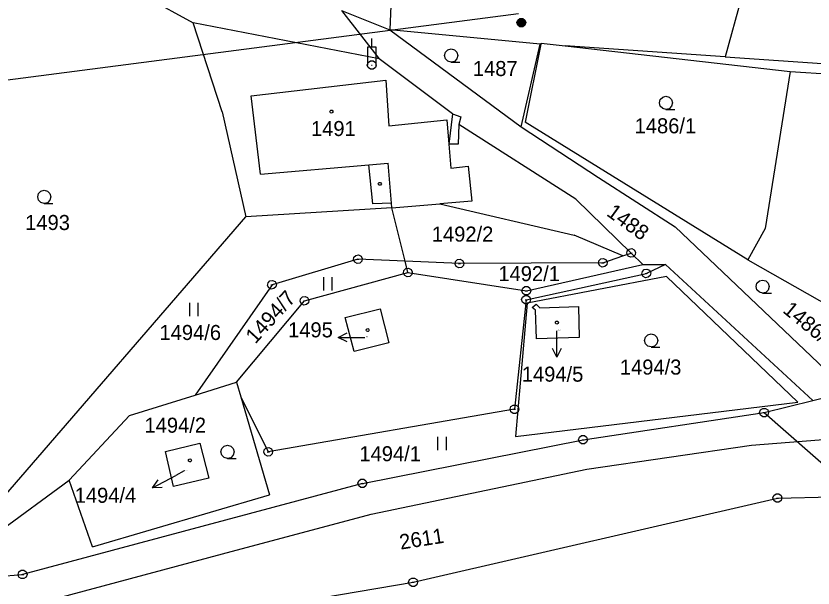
# Model space of a CAD drawing. Extents: x -806774 to -803680, y -1151731 to -1150053.
# Drawn here: x -805353.1 to -805263, y -1150678 to -1150613.4 of the extents above; entities that cross this region are included whole.
import ezdxf

# ---------------------------------------------------------------- set-up
doc = ezdxf.new("R2010")
doc.units = 0
for name, color, linetype in [('1', 7, 'Continuous'), ('12', 7, 'Continuous'), ('2', 7, 'Continuous'), ('3', 7, 'Continuous'), ('4', 7, 'Continuous'), ('5', 7, 'Continuous'), ('6', 7, 'Continuous'), ('7', 7, 'Continuous'), ('8', 7, 'Continuous')]:
    doc.layers.add(name, color=color, linetype=linetype)

msp = doc.modelspace()

# ---------------------------------------------------------------- linework, layer by layer
at = {"layer": '1'}
for p, q in [((-805309.17, -1150577.58), (-805310.84, -1150614.97)), ((-805269.55, -1150605.7), (-805272.94, -1150618.01)), ((-805343.1, -1150608.62), (-805333.04, -1150614.16)), ((-805316.27, -1150612.77), (-805312.03, -1150618.23)), ((-805316.27, -1150612.77), (-805310.84, -1150614.97)), ((-805312.03, -1150618.23), (-805333.04, -1150614.16)), ((-805329.77, -1150624.22), (-805333.04, -1150614.16)), ((-805310.84, -1150614.97), (-805295.98, -1150625.93)), ((-805293.82, -1150616.59), (-805310.84, -1150614.97)), ((-805293.75, -1150616.59), (-805293.73, -1150616.47)), ((-805293.73, -1150616.47), (-805291.03, -1150616.78)), ((-805295.98, -1150625.93), (-805293.82, -1150616.59)), ((-805293.75, -1150616.59), (-805295.53, -1150625.4)), ((-805293.82, -1150616.59), (-805293.75, -1150616.59)), ((-805272.94, -1150618.01), (-805291.03, -1150616.78)), ((-805291.03, -1150616.78), (-805265.57, -1150619.68)), ((-805303.74, -1150624.45), (-805312.03, -1150618.23)), ((-805272.94, -1150618.01), (-805223.94, -1150621.35)), ((-805265.57, -1150619.68), (-805268.41, -1150637.4)), ((-805265.57, -1150619.68), (-805251.46, -1150620.59)), ((-805329.77, -1150624.22), (-805327.08, -1150636.08)), ((-805303.74, -1150624.45), (-805302.8, -1150624.78)), ((-805302.8, -1150624.78), (-805303.02, -1150625.67)), ((-805270.38, -1150640.96), (-805295.53, -1150625.4)), ((-805289.81, -1150634.11), (-805303.02, -1150625.67)), ((-805295.98, -1150625.93), (-805287.25, -1150631.65)), ((-805287.25, -1150631.65), (-805278.6, -1150637.23)), ((-805283.55, -1150640.18), (-805289.81, -1150634.11)), ((-805310.6, -1150635.06), (-805327.08, -1150636.08)), ((-805310.6, -1150635.06), (-805305.16, -1150634.61)), ((-805309.1, -1150641.11), (-805310.6, -1150635.06)), ((-805305.16, -1150634.61), (-805290, -1150638.16)), ((-805362.8, -1150677.38), (-805327.08, -1150636.08)), ((-805278.6, -1150637.23), (-805259.03, -1150655.84)), ((-805284.49, -1150640.51), (-805290, -1150638.16)), ((-805268.41, -1150637.4), (-805270.38, -1150640.96)), ((-805286.74, -1150641.29), (-805284.49, -1150640.51)), ((-805284.49, -1150640.51), (-805283.55, -1150640.18)), ((-805282.22, -1150641.47), (-805283.55, -1150640.18)), ((-805314.43, -1150640.89), (-805324.14, -1150643.77)), ((-805309.1, -1150641.11), (-805314.43, -1150640.89)), ((-805308.78, -1150642.39), (-805309.1, -1150641.11)), ((-805302.95, -1150641.37), (-805309.1, -1150641.11)), ((-805286.74, -1150641.29), (-805302.95, -1150641.37)), ((-805295.4, -1150644.46), (-805282.22, -1150641.47)), ((-805282.22, -1150641.47), (-805279.69, -1150641.49)), ((-805279.69, -1150641.49), (-805281.84, -1150642.49)), ((-805279.69, -1150641.49), (-805263.04, -1150656.84)), ((-805270.38, -1150640.96), (-805257.03, -1150648.53)), ((-805320.46, -1150645.58), (-805308.78, -1150642.39)), ((-805308.78, -1150642.39), (-805295.4, -1150644.46)), ((-805295.42, -1150645.46), (-805281.84, -1150642.49)), ((-805279.55, -1150642.84), (-805295.32, -1150645.83)), ((-805279.55, -1150642.84), (-805264.71, -1150657.04)), ((-805324.14, -1150643.77), (-805332.84, -1150656.24)), ((-805328.16, -1150654.79), (-805320.46, -1150645.58)), ((-805295.42, -1150645.46), (-805296.73, -1150657.84)), ((-805295.32, -1150645.83), (-805296.63, -1150660.91)), ((-805294.74, -1150646.34), (-805294.28, -1150645.95)), ((-805294.28, -1150645.95), (-805293.87, -1150646.39)), ((-805293.87, -1150646.39), (-805289.51, -1150646.21)), ((-805289.51, -1150646.21), (-805289.44, -1150649.72)), ((-805294.35, -1150646.65), (-805294.74, -1150646.34)), ((-805294.25, -1150649.87), (-805294.35, -1150646.65)), ((-805289.44, -1150649.72), (-805294.25, -1150649.87)), ((-805332.84, -1150656.24), (-805328.16, -1150654.79)), ((-805328.16, -1150654.79), (-805327.68, -1150656.42)), ((-805263.04, -1150656.84), (-805259.03, -1150655.84)), ((-805340.26, -1150658.54), (-805332.84, -1150656.24)), ((-805327.68, -1150656.42), (-805324.43, -1150667.5)), ((-805327.68, -1150656.42), (-805324.56, -1150662.66)), ((-805296.63, -1150660.91), (-805264.71, -1150657.04)), ((-805268.53, -1150658.22), (-805263.04, -1150656.84)), ((-805296.73, -1150657.84), (-805324.56, -1150662.66)), ((-805347.06, -1150665.86), (-805340.26, -1150658.54)), ((-805288.99, -1150661.29), (-805268.53, -1150658.22)), ((-805268.53, -1150658.22), (-805257.77, -1150667.64)), ((-805313.93, -1150666.21), (-805288.99, -1150661.29)), ((-805336.17, -1150662.61), (-805332.28, -1150661.68)), ((-805332.28, -1150661.68), (-805331.27, -1150665.63)), ((-805335.28, -1150666.58), (-805336.17, -1150662.61)), ((-805362.8, -1150677.38), (-805347.06, -1150665.86)), ((-805344.42, -1150673.39), (-805347.06, -1150665.86)), ((-805331.27, -1150665.63), (-805335.28, -1150666.58)), ((-805313.93, -1150666.21), (-805352.32, -1150676.52)), ((-805344.42, -1150673.39), (-805324.43, -1150667.5)), ((-805308.19, -1150677.39), (-805267.02, -1150667.87)), ((-805267.02, -1150667.87), (-805257.77, -1150667.64)), ((-805362.8, -1150677.38), (-805352.32, -1150676.52)), ((-805358.57, -1150685.85), (-805308.19, -1150677.39))]:
    msp.add_line(p, q, dxfattribs=at)
at = {"layer": '12'}
for p, q in [((-805326.49, -1150622.4), (-805311.29, -1150620.64)), ((-805311.29, -1150620.64), (-805310.93, -1150625.8)), ((-805325.44, -1150631.26), (-805326.49, -1150622.4)), ((-805310.93, -1150625.8), (-805304.38, -1150625.11)), ((-805304.38, -1150625.11), (-805304.15, -1150627.87)), ((-805304.15, -1150627.87), (-805303.92, -1150630.59)), ((-805313.18, -1150630.2), (-805311.01, -1150630.01)), ((-805310.64, -1150634.56), (-805311.01, -1150630.01)), ((-805325.44, -1150631.26), (-805313.18, -1150630.2)), ((-805303.92, -1150630.59), (-805301.96, -1150630.37)), ((-805301.96, -1150630.37), (-805301.56, -1150634.32)), ((-805310.6, -1150635.06), (-805310.64, -1150634.56)), ((-805301.56, -1150634.32), (-805305.16, -1150634.61)), ((-805310.6, -1150635.06), (-805305.16, -1150634.61)), ((-805294.74, -1150646.34), (-805294.28, -1150645.95)), ((-805294.28, -1150645.95), (-805293.87, -1150646.39)), ((-805293.87, -1150646.39), (-805289.51, -1150646.21)), ((-805289.51, -1150646.21), (-805289.44, -1150649.72)), ((-805315.86, -1150647.46), (-805311.91, -1150646.48)), ((-805311.91, -1150646.48), (-805310.94, -1150650.34)), ((-805294.35, -1150646.65), (-805294.74, -1150646.34)), ((-805294.25, -1150649.87), (-805294.35, -1150646.65)), ((-805314.84, -1150651.32), (-805315.86, -1150647.46)), ((-805289.44, -1150649.72), (-805294.25, -1150649.87)), ((-805310.94, -1150650.34), (-805314.84, -1150651.32)), ((-805336.17, -1150662.61), (-805332.28, -1150661.68)), ((-805332.28, -1150661.68), (-805331.27, -1150665.63)), ((-805335.28, -1150666.58), (-805336.17, -1150662.61)), ((-805331.27, -1150665.63), (-805335.28, -1150666.58))]:
    msp.add_line(p, q, dxfattribs=at)
at = {"layer": '3'}
for p, q in [((-805318.33, -1150642.92), (-805318.33, -1150644.42)), ((-805317.33, -1150644.42), (-805317.33, -1150642.92)), ((-805333.48, -1150645.81), (-805333.48, -1150647.31)), ((-805332.48, -1150647.31), (-805332.48, -1150645.81)), ((-805305.43, -1150660.95), (-805305.43, -1150662.45)), ((-805304.43, -1150662.45), (-805304.43, -1150660.95))]:
    msp.add_line(p, q, dxfattribs=at)
for points in [[(-805303.88, -1150618.6), (-805304.26, -1150618.5), (-805304.53, -1150618.23), (-805304.63, -1150617.86), (-805304.53, -1150617.49), (-805304.26, -1150617.22), (-805303.89, -1150617.12), (-805303.52, -1150617.22), (-805303.25, -1150617.49), (-805303.15, -1150617.87), (-805303.25, -1150618.25), (-805303.52, -1150618.52), (-805303.9, -1150618.62), (-805302.9, -1150618.62)], [(-805279.61, -1150623.95), (-805279.99, -1150623.85), (-805280.26, -1150623.58), (-805280.36, -1150623.21), (-805280.26, -1150622.84), (-805279.99, -1150622.57), (-805279.62, -1150622.47), (-805279.25, -1150622.57), (-805278.98, -1150622.84), (-805278.88, -1150623.22), (-805278.98, -1150623.6), (-805279.25, -1150623.87), (-805279.63, -1150623.97), (-805278.63, -1150623.97)], [(-805349.87, -1150634.57), (-805350.25, -1150634.47), (-805350.52, -1150634.2), (-805350.62, -1150633.83), (-805350.52, -1150633.46), (-805350.25, -1150633.19), (-805349.88, -1150633.09), (-805349.51, -1150633.19), (-805349.24, -1150633.46), (-805349.14, -1150633.84), (-805349.24, -1150634.22), (-805349.51, -1150634.49), (-805349.89, -1150634.59), (-805348.89, -1150634.59)], [(-805268.69, -1150644.71), (-805269.07, -1150644.61), (-805269.34, -1150644.34), (-805269.44, -1150643.97), (-805269.34, -1150643.6), (-805269.07, -1150643.33), (-805268.7, -1150643.23), (-805268.33, -1150643.33), (-805268.06, -1150643.6), (-805267.96, -1150643.98), (-805268.06, -1150644.36), (-805268.33, -1150644.63), (-805268.71, -1150644.73), (-805267.71, -1150644.73)], [(-805281.28, -1150650.8), (-805281.66, -1150650.7), (-805281.93, -1150650.43), (-805282.03, -1150650.06), (-805281.93, -1150649.69), (-805281.66, -1150649.42), (-805281.29, -1150649.32), (-805280.92, -1150649.42), (-805280.65, -1150649.69), (-805280.55, -1150650.07), (-805280.65, -1150650.45), (-805280.92, -1150650.72), (-805281.3, -1150650.82), (-805280.3, -1150650.82)], [(-805329.16, -1150663.39), (-805329.54, -1150663.29), (-805329.81, -1150663.02), (-805329.91, -1150662.65), (-805329.81, -1150662.28), (-805329.54, -1150662.01), (-805329.17, -1150661.91), (-805328.8, -1150662.01), (-805328.53, -1150662.28), (-805328.43, -1150662.66), (-805328.53, -1150663.04), (-805328.8, -1150663.31), (-805329.18, -1150663.41), (-805328.18, -1150663.41)]]:
    msp.add_lwpolyline(points, dxfattribs=at)
at = {"layer": '4'}
for p, q in [((-805326.49, -1150622.4), (-805311.29, -1150620.64)), ((-805311.29, -1150620.64), (-805310.93, -1150625.8)), ((-805325.44, -1150631.26), (-805326.49, -1150622.4)), ((-805303.74, -1150624.45), (-805304.15, -1150627.87)), ((-805310.93, -1150625.8), (-805304.38, -1150625.11)), ((-805304.38, -1150625.11), (-805304.15, -1150627.87)), ((-805303.02, -1150625.67), (-805303.1, -1150627.89)), ((-805303.1, -1150627.89), (-805304.15, -1150627.87)), ((-805304.15, -1150627.87), (-805303.92, -1150630.59)), ((-805313.18, -1150630.2), (-805311.01, -1150630.01)), ((-805310.64, -1150634.56), (-805311.01, -1150630.01)), ((-805325.44, -1150631.26), (-805313.18, -1150630.2)), ((-805312.75, -1150634.63), (-805313.18, -1150630.2)), ((-805303.92, -1150630.59), (-805301.96, -1150630.37)), ((-805301.96, -1150630.37), (-805301.56, -1150634.32)), ((-805310.64, -1150634.56), (-805312.75, -1150634.63)), ((-805310.6, -1150635.06), (-805310.64, -1150634.56)), ((-805301.56, -1150634.32), (-805305.16, -1150634.61)), ((-805315.86, -1150647.46), (-805311.91, -1150646.48)), ((-805311.91, -1150646.48), (-805310.94, -1150650.34)), ((-805314.84, -1150651.32), (-805315.86, -1150647.46)), ((-805310.94, -1150650.34), (-805314.84, -1150651.32))]:
    msp.add_line(p, q, dxfattribs=at)
at = {"layer": '5'}
for points in [[(-805317.43, -1150624.02), (-805317.33, -1150624.04), (-805317.28, -1150624.13), (-805317.26, -1150624.19), (-805317.28, -1150624.28), (-805317.36, -1150624.35), (-805317.43, -1150624.36), (-805317.52, -1150624.33), (-805317.58, -1150624.27), (-805317.6, -1150624.19), (-805317.58, -1150624.1), (-805317.5, -1150624.03)], [(-805311.87, -1150632.21), (-805311.78, -1150632.36), (-805311.87, -1150632.51), (-805312.05, -1150632.51), (-805312.14, -1150632.36), (-805312.05, -1150632.21)], [(-805291.95, -1150647.87), (-805291.85, -1150647.89), (-805291.8, -1150647.98), (-805291.78, -1150648.04), (-805291.8, -1150648.13), (-805291.88, -1150648.2), (-805291.95, -1150648.21), (-805292.04, -1150648.18), (-805292.1, -1150648.12), (-805292.12, -1150648.04), (-805292.1, -1150647.95), (-805292.02, -1150647.88)], [(-805313.33, -1150648.72), (-805313.23, -1150648.74), (-805313.18, -1150648.83), (-805313.16, -1150648.89), (-805313.18, -1150648.98), (-805313.26, -1150649.05), (-805313.33, -1150649.06), (-805313.42, -1150649.03), (-805313.48, -1150648.97), (-805313.5, -1150648.89), (-805313.48, -1150648.8), (-805313.4, -1150648.73)], [(-805333.42, -1150663.45), (-805333.32, -1150663.47), (-805333.27, -1150663.56), (-805333.25, -1150663.62), (-805333.27, -1150663.71), (-805333.35, -1150663.78), (-805333.42, -1150663.79), (-805333.51, -1150663.76), (-805333.57, -1150663.7), (-805333.59, -1150663.62), (-805333.57, -1150663.53), (-805333.49, -1150663.46)]]:
    msp.add_lwpolyline(points, close=True, dxfattribs=at)
at = {"layer": '6'}
for p, q in [((-805357.77, -1150621.1), (-805296.28, -1150613.1)), ((-805312.86, -1150616.93), (-805312.86, -1150615.93)), ((-805312.91, -1150618.93), (-805312.81, -1150618.93)), ((-805269.95, -1150661.91), (-805251.1, -1150660.35)), ((-805288.57, -1150664.59), (-805269.95, -1150661.91)), ((-805312.93, -1150669.71), (-805288.57, -1150664.59)), ((-805329.72, -1150674.16), (-805312.93, -1150669.71)), ((-805358.86, -1150681.97), (-805329.72, -1150674.16))]:
    msp.add_line(p, q, dxfattribs=at)
for points in [[(-805296.12, -1150613.67), (-805295.81, -1150613.67), (-805295.56, -1150613.85), (-805295.46, -1150614.14), (-805295.56, -1150614.43), (-805295.81, -1150614.61), (-805296.12, -1150614.61), (-805296.37, -1150614.43), (-805296.47, -1150614.14), (-805296.37, -1150613.85), (-805296.12, -1150613.67), (-805296.09, -1150613.71), (-805295.85, -1150613.71), (-805295.69, -1150613.79), (-805296.25, -1150613.79), (-805296.33, -1150613.87), (-805295.61, -1150613.87), (-805295.61, -1150613.95), (-805296.33, -1150613.95), (-805296.37, -1150614.03), (-805295.57, -1150614.03), (-805295.53, -1150614.11), (-805296.41, -1150614.11), (-805296.41, -1150614.19), (-805295.53, -1150614.19), (-805295.56, -1150614.27), (-805296.37, -1150614.27), (-805296.36, -1150614.35), (-805295.55, -1150614.35), (-805295.6, -1150614.43), (-805296.32, -1150614.43), (-805296.24, -1150614.51), (-805295.68, -1150614.51), (-805295.79, -1150614.59), (-805296.13, -1150614.59)], [(-805312.36, -1150618.93), (-805312.46, -1150619.22), (-805312.71, -1150619.4), (-805313.02, -1150619.4), (-805313.27, -1150619.22), (-805313.37, -1150618.93), (-805313.27, -1150618.64), (-805313.02, -1150618.46), (-805312.71, -1150618.46), (-805312.46, -1150618.64), (-805312.36, -1150618.93), (-805312.36, -1150617.66), (-805312.36, -1150616.93), (-805312.86, -1150616.93), (-805313.36, -1150616.93), (-805313.36, -1150618.2), (-805313.36, -1150618.93)], [(-805312.91, -1150618.93), (-805312.86, -1150618.93), (-805312.81, -1150618.93)]]:
    msp.add_lwpolyline(points, dxfattribs=at)
at = {"layer": '7'}
for p, q in [((-805291.949, -1150651.96), (-805291.95, -1150648.96)), ((-805316.65, -1150649.711), (-805313.65, -1150649.71)), ((-805334.06, -1150664.81), (-805335, -1150665.31)), ((-805337.651, -1150666.714), (-805335, -1150665.31))]:
    msp.add_line(p, q, dxfattribs=at)
for points in [[(-805315.65, -1150650.21), (-805316.65, -1150649.711), (-805315.65, -1150649.21)], [(-805291.449, -1150650.96), (-805291.949, -1150651.96), (-805292.449, -1150650.96)], [(-805336.533, -1150666.688), (-805337.651, -1150666.714), (-805337.001, -1150665.804)]]:
    msp.add_lwpolyline(points, dxfattribs=at)
at = {"layer": '8'}
for p, q in [((-805314.549, -1150640.909), (-805314.311, -1150640.871)), ((-805283.669, -1150640.199), (-805283.431, -1150640.161)), ((-805303.069, -1150641.389), (-805302.831, -1150641.351)), ((-805286.859, -1150641.309), (-805286.621, -1150641.271)), ((-805308.899, -1150642.409), (-805308.661, -1150642.371)), ((-805281.959, -1150642.509), (-805281.721, -1150642.471)), ((-805324.259, -1150643.789), (-805324.021, -1150643.751)), ((-805295.52, -1150644.46), (-805295.28, -1150644.46)), ((-805320.579, -1150645.599), (-805320.341, -1150645.561)), ((-805295.54, -1150645.46), (-805295.3, -1150645.46)), ((-805296.85, -1150657.84), (-805296.61, -1150657.84)), ((-805268.65, -1150658.22), (-805268.41, -1150658.22)), ((-805289.11, -1150661.29), (-805288.87, -1150661.29)), ((-805324.679, -1150662.679), (-805324.441, -1150662.641)), ((-805314.05, -1150666.21), (-805313.81, -1150666.21)), ((-805267.14, -1150667.87), (-805266.9, -1150667.87)), ((-805352.44, -1150676.52), (-805352.2, -1150676.52)), ((-805308.31, -1150677.39), (-805308.07, -1150677.39))]:
    msp.add_line(p, q, dxfattribs=at)
for points in [[(-805283.477, -1150639.682), (-805283.202, -1150639.821), (-805283.058, -1150640.092), (-805283.111, -1150640.394), (-805283.33, -1150640.611), (-805283.636, -1150640.659), (-805283.911, -1150640.521), (-805284.055, -1150640.25), (-805284.002, -1150639.948), (-805283.783, -1150639.731)], [(-805314.357, -1150640.392), (-805314.082, -1150640.531), (-805313.938, -1150640.802), (-805313.991, -1150641.104), (-805314.21, -1150641.321), (-805314.516, -1150641.369), (-805314.791, -1150641.231), (-805314.935, -1150640.96), (-805314.882, -1150640.658), (-805314.663, -1150640.441)], [(-805302.877, -1150640.872), (-805302.602, -1150641.011), (-805302.458, -1150641.282), (-805302.511, -1150641.584), (-805302.73, -1150641.801), (-805303.036, -1150641.849), (-805303.311, -1150641.711), (-805303.455, -1150641.44), (-805303.402, -1150641.138), (-805303.183, -1150640.921)], [(-805286.667, -1150640.792), (-805286.392, -1150640.931), (-805286.248, -1150641.202), (-805286.301, -1150641.504), (-805286.52, -1150641.721), (-805286.826, -1150641.769), (-805287.101, -1150641.631), (-805287.245, -1150641.36), (-805287.192, -1150641.058), (-805286.973, -1150640.841)], [(-805308.707, -1150641.892), (-805308.432, -1150642.031), (-805308.288, -1150642.302), (-805308.341, -1150642.604), (-805308.56, -1150642.821), (-805308.866, -1150642.869), (-805309.141, -1150642.731), (-805309.285, -1150642.46), (-805309.232, -1150642.158), (-805309.013, -1150641.941)], [(-805281.767, -1150641.992), (-805281.492, -1150642.131), (-805281.348, -1150642.402), (-805281.401, -1150642.704), (-805281.62, -1150642.921), (-805281.926, -1150642.969), (-805282.201, -1150642.831), (-805282.345, -1150642.56), (-805282.292, -1150642.258), (-805282.073, -1150642.041)], [(-805324.067, -1150643.272), (-805323.792, -1150643.411), (-805323.648, -1150643.682), (-805323.701, -1150643.984), (-805323.92, -1150644.201), (-805324.226, -1150644.249), (-805324.501, -1150644.111), (-805324.645, -1150643.84), (-805324.592, -1150643.538), (-805324.373, -1150643.321)], [(-805295.25, -1150643.98), (-805295, -1150644.16), (-805294.9, -1150644.45), (-805295, -1150644.74), (-805295.25, -1150644.92), (-805295.56, -1150644.92), (-805295.81, -1150644.74), (-805295.91, -1150644.45), (-805295.81, -1150644.16), (-805295.56, -1150643.98)], [(-805320.387, -1150645.082), (-805320.112, -1150645.221), (-805319.968, -1150645.492), (-805320.021, -1150645.794), (-805320.24, -1150646.011), (-805320.546, -1150646.059), (-805320.821, -1150645.921), (-805320.965, -1150645.65), (-805320.912, -1150645.348), (-805320.693, -1150645.131)], [(-805295.27, -1150644.98), (-805295.02, -1150645.16), (-805294.92, -1150645.45), (-805295.02, -1150645.74), (-805295.27, -1150645.92), (-805295.58, -1150645.92), (-805295.83, -1150645.74), (-805295.93, -1150645.45), (-805295.83, -1150645.16), (-805295.58, -1150644.98)], [(-805296.58, -1150657.36), (-805296.33, -1150657.54), (-805296.23, -1150657.83), (-805296.33, -1150658.12), (-805296.58, -1150658.3), (-805296.89, -1150658.3), (-805297.14, -1150658.12), (-805297.24, -1150657.83), (-805297.14, -1150657.54), (-805296.89, -1150657.36)], [(-805268.38, -1150657.74), (-805268.13, -1150657.92), (-805268.03, -1150658.21), (-805268.13, -1150658.5), (-805268.38, -1150658.68), (-805268.69, -1150658.68), (-805268.94, -1150658.5), (-805269.04, -1150658.21), (-805268.94, -1150657.92), (-805268.69, -1150657.74)], [(-805288.84, -1150660.81), (-805288.59, -1150660.99), (-805288.49, -1150661.28), (-805288.59, -1150661.57), (-805288.84, -1150661.75), (-805289.15, -1150661.75), (-805289.4, -1150661.57), (-805289.5, -1150661.28), (-805289.4, -1150660.99), (-805289.15, -1150660.81)], [(-805324.487, -1150662.162), (-805324.212, -1150662.301), (-805324.068, -1150662.572), (-805324.121, -1150662.874), (-805324.34, -1150663.091), (-805324.646, -1150663.139), (-805324.921, -1150663.001), (-805325.065, -1150662.73), (-805325.012, -1150662.428), (-805324.793, -1150662.211)], [(-805313.78, -1150665.73), (-805313.53, -1150665.91), (-805313.43, -1150666.2), (-805313.53, -1150666.49), (-805313.78, -1150666.67), (-805314.09, -1150666.67), (-805314.34, -1150666.49), (-805314.44, -1150666.2), (-805314.34, -1150665.91), (-805314.09, -1150665.73)], [(-805266.87, -1150667.39), (-805266.62, -1150667.57), (-805266.52, -1150667.86), (-805266.62, -1150668.15), (-805266.87, -1150668.33), (-805267.18, -1150668.33), (-805267.43, -1150668.15), (-805267.53, -1150667.86), (-805267.43, -1150667.57), (-805267.18, -1150667.39)], [(-805352.17, -1150676.04), (-805351.92, -1150676.22), (-805351.82, -1150676.51), (-805351.92, -1150676.8), (-805352.17, -1150676.98), (-805352.48, -1150676.98), (-805352.73, -1150676.8), (-805352.83, -1150676.51), (-805352.73, -1150676.22), (-805352.48, -1150676.04)], [(-805308.04, -1150676.91), (-805307.79, -1150677.09), (-805307.69, -1150677.38), (-805307.79, -1150677.67), (-805308.04, -1150677.85), (-805308.35, -1150677.85), (-805308.6, -1150677.67), (-805308.7, -1150677.38), (-805308.6, -1150677.09), (-805308.35, -1150676.91)]]:
    msp.add_lwpolyline(points, close=True, dxfattribs=at)

# ---------------------------------------------------------------- texts
at = {"layer": '2'}
for s, height, p in [('1487', 1.7, (-805301.442, -1150620.18)), ('1491', 1.7, (-805319.737, -1150626.96)), ('1486/1', 1.7, (-805283.163, -1150626.65)), ('1493', 1.7, (-805352.032, -1150637.58)), ('1492/2', 1.7, (-805306.082, -1150638.89)), ('1492/1', 1.7, (-805298.56, -1150643.36)), ('1494/6', 1.7, (-805336.854, -1150650.01)), ('1494/5', 0.1, (-805291.927, -1150648.96)), ('1495', 0.1, (-805313.627, -1150649.71)), ('1494/3', 1.7, (-805284.831, -1150653.92)), ('1494/2', 1.7, (-805338.548, -1150660.49)), ('1494/1', 1.7, (-805314.266, -1150663.71)), ('1494/4', 0.1, (-805334.037, -1150664.81))]:
    msp.add_text(s, height=height, dxfattribs=at).set_placement(p)
for s, rotation, p in [('1488', 324.00763, (-805286.445, -1150635.871)), ('1494/7', 47.61279, (-805326.03, -1150650.531)), ('1486/6', 320.56989, (-805266.526, -1150646.812)), ('2611', 8.99544, (-805309.603, -1150673.706))]:
    msp.add_text(s, height=1.7, rotation=rotation, dxfattribs=at).set_placement(p)
at = {"layer": '7'}
for s, p in [('1495', (-805322.323, -1150649.71)), ('1494/5', (-805295.911, -1150654.72)), ('1494/4', (-805346.437, -1150668.41))]:
    msp.add_text(s, height=1.7, dxfattribs=at).set_placement(p)

doc.saveas('drawing.dxf')
